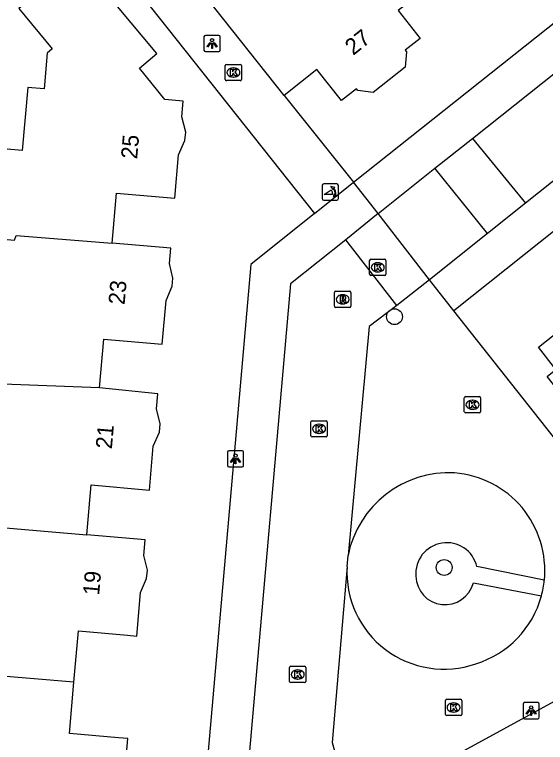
# Model space of a CAD drawing. Extents: x 159628 to 160723, y 388176 to 389416.
# Drawn here: x 160028.09 to 160060.72, y 388521.02 to 388565.76 of the extents above; entities that cross this region are included whole.
import ezdxf

# ---------------------------------------------------------------- set-up
doc = ezdxf.new("R2010")
doc.units = 0
for name, color, linetype in [('IMGEO_Boom', 7, 'Continuous'), ('IMGEO_Kolk', 7, 'Continuous'), ('IMGEO_Lichtpunt', 7, 'Continuous'), ('IMGEO_Pand', 7, 'Continuous'), ('IMGEO_Pand_nummerreeks', 7, 'Continuous'), ('IMGEO_Poller', 7, 'Continuous'), ('IMGEO_Rijbaan_lokaal_open', 7, 'Continuous'), ('IMGEO_Rioolput', 7, 'Continuous'), ('IMGEO_Voetpad_halfverhard', 7, 'Continuous'), ('IMGEO_Voetpad_open', 7, 'Continuous')]:
    doc.layers.add(name, color=color, linetype=linetype)

msp = doc.modelspace()

# ---------------------------------------------------------------- linework, layer by layer
at = {"layer": 'IMGEO_Boom'}
for centre in [(160051.439, 388547.193), (160054.494, 388531.775)]:
    msp.add_circle(centre, 0.489, dxfattribs=at)
at = {"layer": 'IMGEO_Kolk'}
for p, q in [((160041.035, 388561.774), (160041.035, 388562.626)), ((160041.11, 388562.7), (160041.962, 388562.7)), ((160041.523, 388562.48), (160041.548, 388562.48)), ((160042.036, 388562.626), (160042.036, 388561.774)), ((160041.962, 388561.7), (160041.11, 388561.7)), ((160041.546, 388561.92), (160041.521, 388561.92)), ((160049.912, 388549.798), (160049.912, 388550.65)), ((160049.987, 388550.724), (160050.839, 388550.724)), ((160050.4, 388550.504), (160050.425, 388550.504)), ((160050.913, 388550.65), (160050.913, 388549.798)), ((160050.423, 388549.944), (160050.398, 388549.944)), ((160050.839, 388549.724), (160049.987, 388549.724)), ((160055.731, 388541.354), (160055.731, 388542.206)), ((160055.806, 388542.28), (160056.658, 388542.28)), ((160056.219, 388542.06), (160056.244, 388542.06)), ((160056.732, 388542.206), (160056.732, 388541.354)), ((160056.242, 388541.5), (160056.217, 388541.5)), ((160056.658, 388541.28), (160055.806, 388541.28)), ((160046.304, 388539.874), (160046.304, 388540.726)), ((160046.379, 388540.8), (160047.231, 388540.8)), ((160046.792, 388540.58), (160046.817, 388540.58)), ((160047.305, 388540.726), (160047.305, 388539.874)), ((160047.231, 388539.8), (160046.379, 388539.8)), ((160046.815, 388540.02), (160046.79, 388540.02)), ((160044.989, 388524.776), (160044.989, 388525.628)), ((160045.064, 388525.702), (160045.916, 388525.702)), ((160045.477, 388525.482), (160045.502, 388525.482)), ((160045.99, 388525.628), (160045.99, 388524.776)), ((160045.5, 388524.922), (160045.475, 388524.922)), ((160045.916, 388524.702), (160045.064, 388524.702)), ((160054.571, 388522.747), (160054.571, 388523.599)), ((160054.646, 388523.673), (160055.498, 388523.673)), ((160055.572, 388523.599), (160055.572, 388522.747)), ((160055.059, 388523.453), (160055.084, 388523.453)), ((160055.498, 388522.673), (160054.646, 388522.673)), ((160055.082, 388522.893), (160055.057, 388522.893))]:
    msp.add_line(p, q, dxfattribs=at)
for points in [[(160041.035, 388561.774), (160041.035, 388562.626)], [(160041.11, 388562.7), (160041.962, 388562.7)], [(160042.036, 388562.626), (160042.036, 388561.774)], [(160041.356, 388562.4), (160041.479, 388562.4), (160041.479, 388562.249), (160041.609, 388562.4), (160041.773, 388562.4), (160041.627, 388562.249), (160041.78, 388562), (160041.628, 388562), (160041.543, 388562.164), (160041.479, 388562.097), (160041.479, 388562), (160041.356, 388562), (160041.356, 388562.4)], [(160041.962, 388561.7), (160041.11, 388561.7)], [(160049.912, 388549.798), (160049.912, 388550.65)], [(160049.987, 388550.724), (160050.839, 388550.724)], [(160050.233, 388550.424), (160050.356, 388550.424), (160050.356, 388550.273), (160050.486, 388550.424), (160050.65, 388550.424), (160050.504, 388550.273), (160050.657, 388550.024), (160050.505, 388550.024), (160050.42, 388550.188), (160050.356, 388550.121), (160050.356, 388550.024), (160050.233, 388550.024), (160050.233, 388550.424)], [(160050.913, 388550.65), (160050.913, 388549.798)], [(160050.839, 388549.724), (160049.987, 388549.724)], [(160055.731, 388541.354), (160055.731, 388542.206)], [(160055.806, 388542.28), (160056.658, 388542.28)], [(160056.052, 388541.98), (160056.175, 388541.98), (160056.175, 388541.829), (160056.305, 388541.98), (160056.469, 388541.98), (160056.323, 388541.829), (160056.476, 388541.58), (160056.324, 388541.58), (160056.239, 388541.744), (160056.175, 388541.677), (160056.175, 388541.58), (160056.052, 388541.58), (160056.052, 388541.98)], [(160056.732, 388542.206), (160056.732, 388541.354)], [(160056.658, 388541.28), (160055.806, 388541.28)], [(160046.304, 388539.874), (160046.304, 388540.726)], [(160046.379, 388540.8), (160047.231, 388540.8)], [(160047.305, 388540.726), (160047.305, 388539.874)], [(160046.625, 388540.5), (160046.748, 388540.5), (160046.748, 388540.349), (160046.878, 388540.5), (160047.042, 388540.5), (160046.896, 388540.349), (160047.049, 388540.1), (160046.897, 388540.1), (160046.812, 388540.264), (160046.748, 388540.197), (160046.748, 388540.1), (160046.625, 388540.1), (160046.625, 388540.5)], [(160047.231, 388539.8), (160046.379, 388539.8)], [(160044.989, 388524.776), (160044.989, 388525.628)], [(160045.064, 388525.702), (160045.916, 388525.702)], [(160045.31, 388525.402), (160045.433, 388525.402), (160045.433, 388525.251), (160045.563, 388525.402), (160045.727, 388525.402), (160045.581, 388525.251), (160045.734, 388525.002), (160045.582, 388525.002), (160045.497, 388525.166), (160045.433, 388525.099), (160045.433, 388525.002), (160045.31, 388525.002), (160045.31, 388525.402)], [(160045.99, 388525.628), (160045.99, 388524.776)], [(160045.916, 388524.702), (160045.064, 388524.702)], [(160054.571, 388522.747), (160054.571, 388523.599)], [(160054.646, 388523.673), (160055.498, 388523.673)], [(160055.572, 388523.599), (160055.572, 388522.747)], [(160054.892, 388523.373), (160055.015, 388523.373), (160055.015, 388523.222), (160055.145, 388523.373), (160055.309, 388523.373), (160055.163, 388523.222), (160055.316, 388522.973), (160055.164, 388522.973), (160055.079, 388523.137), (160055.015, 388523.07), (160055.015, 388522.973), (160054.892, 388522.973), (160054.892, 388523.373)], [(160055.498, 388522.673), (160054.646, 388522.673)]]:
    msp.add_lwpolyline(points, dxfattribs=at)
for centre, start, end in [((160041.112, 388562.624), 91.552, 178.448), ((160041.112, 388562.624), 91.552, 178.448), ((160041.96, 388562.624), 1.552, 88.448), ((160041.96, 388562.624), 1.552, 88.448), ((160041.112, 388561.776), 181.552, 268.448), ((160041.112, 388561.776), 181.552, 268.448), ((160041.96, 388561.776), 271.552, 358.448), ((160041.96, 388561.776), 271.552, 358.448), ((160049.989, 388550.648), 91.552, 178.448), ((160049.989, 388550.648), 91.552, 178.448), ((160050.837, 388550.648), 1.552, 88.448), ((160050.837, 388550.648), 1.552, 88.448), ((160049.989, 388549.8), 181.552, 268.448), ((160049.989, 388549.8), 181.552, 268.448), ((160050.837, 388549.8), 271.552, 358.448), ((160050.837, 388549.8), 271.552, 358.448), ((160055.808, 388542.204), 91.552, 178.448), ((160055.808, 388542.204), 91.552, 178.448), ((160056.656, 388542.204), 1.552, 88.448), ((160056.656, 388542.204), 1.552, 88.448), ((160055.808, 388541.356), 181.552, 268.448), ((160055.808, 388541.356), 181.552, 268.448), ((160056.656, 388541.356), 271.552, 358.448), ((160056.656, 388541.356), 271.552, 358.448), ((160046.381, 388540.724), 91.552, 178.448), ((160046.381, 388540.724), 91.552, 178.448), ((160047.229, 388540.724), 1.552, 88.448), ((160047.229, 388540.724), 1.552, 88.448), ((160046.381, 388539.876), 181.552, 268.448), ((160046.381, 388539.876), 181.552, 268.448), ((160047.229, 388539.876), 271.552, 358.448), ((160047.229, 388539.876), 271.552, 358.448), ((160045.066, 388525.626), 91.552, 178.448), ((160045.066, 388525.626), 91.552, 178.448), ((160045.914, 388525.626), 1.552, 88.448), ((160045.914, 388525.626), 1.552, 88.448), ((160045.066, 388524.778), 181.552, 268.448), ((160045.066, 388524.778), 181.552, 268.448), ((160045.914, 388524.778), 271.552, 358.448), ((160045.914, 388524.778), 271.552, 358.448), ((160054.648, 388523.597), 91.552, 178.448), ((160054.648, 388523.597), 91.552, 178.448), ((160055.496, 388523.597), 1.552, 88.448), ((160055.496, 388523.597), 1.552, 88.448), ((160054.648, 388522.749), 181.552, 268.448), ((160054.648, 388522.749), 181.552, 268.448), ((160055.496, 388522.749), 271.552, 358.448), ((160055.496, 388522.749), 271.552, 358.448)]:
    msp.add_arc(centre, 0.0765, start, end, dxfattribs=at)
for centre, major_axis, ratio, start_param, end_param in [((160041.522, 388562.2), (-0.387, 0.002), 0.722429, 4.712389, 7.853982), ((160041.547, 388562.2), (-0.39, 0.002), 0.717154, 1.570796, 4.712389), ((160050.399, 388550.224), (-0.387, 0.002), 0.722429, 4.712389, 7.853982), ((160050.424, 388550.224), (-0.39, 0.002), 0.717154, 1.570796, 4.712389), ((160056.218, 388541.78), (-0.387, 0.002), 0.722429, 4.712389, 7.853982), ((160056.243, 388541.78), (-0.39, 0.002), 0.717154, 1.570796, 4.712389), ((160046.791, 388540.3), (-0.387, 0.002), 0.722429, 4.712389, 7.853982), ((160046.816, 388540.3), (-0.39, 0.002), 0.717154, 1.570796, 4.712389), ((160045.476, 388525.202), (-0.387, 0.002), 0.722429, 4.712389, 7.853982), ((160045.501, 388525.202), (-0.39, 0.002), 0.717154, 1.570796, 4.712389), ((160055.058, 388523.173), (-0.387, 0.002), 0.722429, 4.712389, 7.853982), ((160055.083, 388523.173), (-0.39, 0.002), 0.717154, 1.570796, 4.712389)]:
    msp.add_ellipse(centre, major_axis=major_axis, ratio=ratio, start_param=start_param, end_param=end_param, dxfattribs=at)
at = {"layer": 'IMGEO_Lichtpunt'}
for p, q in [((160039.73, 388564.39), (160039.73, 388563.583)), ((160039.73, 388564.39), (160039.73, 388563.583)), ((160040.632, 388564.485), (160039.824, 388564.485)), ((160040.632, 388564.485), (160039.824, 388564.485)), ((160040.726, 388563.583), (160040.726, 388564.39)), ((160040.726, 388563.583), (160040.726, 388564.39)), ((160039.824, 388563.489), (160040.632, 388563.489)), ((160039.824, 388563.489), (160040.632, 388563.489)), ((160041.17, 388538.86), (160041.17, 388538.053)), ((160041.17, 388538.86), (160041.17, 388538.053)), ((160042.072, 388538.955), (160041.264, 388538.955)), ((160042.072, 388538.955), (160041.264, 388538.955)), ((160042.166, 388538.053), (160042.166, 388538.86)), ((160042.166, 388538.053), (160042.166, 388538.86)), ((160041.264, 388537.959), (160042.072, 388537.959)), ((160041.264, 388537.959), (160042.072, 388537.959)), ((160059.341, 388523.378), (160059.341, 388522.571)), ((160059.341, 388523.378), (160059.341, 388522.571)), ((160060.243, 388523.473), (160059.435, 388523.473)), ((160060.243, 388523.473), (160059.435, 388523.473)), ((160060.337, 388522.571), (160060.337, 388523.378)), ((160060.337, 388522.571), (160060.337, 388523.378)), ((160059.435, 388522.477), (160060.243, 388522.477)), ((160059.435, 388522.477), (160060.243, 388522.477))]:
    msp.add_line(p, q, dxfattribs=at)
for points in [[(160040.104, 388564.054), (160040.143, 388564.026), (160039.955, 388563.764), (160039.917, 388563.791), (160040.104, 388564.054)], [(160040.206, 388564.006), (160040.253, 388564.006), (160040.253, 388563.684), (160040.206, 388563.684), (160040.206, 388564.006)], [(160040.316, 388564.026), (160040.354, 388564.053), (160040.541, 388563.791), (160040.502, 388563.763), (160040.316, 388564.026)], [(160041.544, 388538.524), (160041.583, 388538.496), (160041.395, 388538.234), (160041.357, 388538.261), (160041.544, 388538.524)], [(160041.646, 388538.476), (160041.693, 388538.476), (160041.693, 388538.154), (160041.646, 388538.154), (160041.646, 388538.476)], [(160041.756, 388538.496), (160041.794, 388538.523), (160041.981, 388538.261), (160041.942, 388538.233), (160041.756, 388538.496)], [(160059.715, 388523.042), (160059.754, 388523.014), (160059.566, 388522.752), (160059.528, 388522.779), (160059.715, 388523.042)], [(160059.817, 388522.994), (160059.864, 388522.994), (160059.864, 388522.672), (160059.817, 388522.672), (160059.817, 388522.994)], [(160059.927, 388523.014), (160059.965, 388523.041), (160060.152, 388522.779), (160060.113, 388522.751), (160059.927, 388523.014)]]:
    msp.add_lwpolyline(points, dxfattribs=at)
for centre in [(160040.229, 388564.188), (160041.669, 388538.658), (160059.84, 388523.176)]:
    msp.add_circle(centre, 0.0994, dxfattribs=at)
for centre, start, end in [((160039.824, 388564.39), 90, 180), ((160039.824, 388564.39), 90, 180), ((160040.632, 388564.39), 0, 90), ((160040.632, 388564.39), 0, 90), ((160039.824, 388563.583), 180, 270), ((160039.824, 388563.583), 180, 270), ((160040.632, 388563.583), 270, 0), ((160040.632, 388563.583), 270, 360), ((160041.264, 388538.86), 90, 180), ((160041.264, 388538.86), 90, 180), ((160042.072, 388538.86), 0, 90), ((160042.072, 388538.86), 0, 90), ((160041.264, 388538.053), 180, 270), ((160041.264, 388538.053), 180, 270), ((160042.072, 388538.053), 270, 0), ((160042.072, 388538.053), 270, 360), ((160059.435, 388523.378), 90, 180), ((160059.435, 388523.378), 90, 180), ((160060.243, 388523.378), 0, 90), ((160060.243, 388523.378), 0, 90), ((160059.435, 388522.571), 180, 270), ((160059.435, 388522.571), 180, 270), ((160060.243, 388522.571), 270, 0), ((160060.243, 388522.571), 270, 360)]:
    msp.add_arc(centre, 0.0946, start, end, dxfattribs=at)
at = {"layer": 'IMGEO_Pand'}
for points in [[(160034.086, 388551.708), (160034.354, 388554.784), (160037.94, 388554.471), (160038.171, 388557.131), (160038.561, 388558.032), (160038.604, 388558.53), (160038.376, 388559.484), (160038.46, 388560.448), (160037.324, 388560.547), (160035.77, 388562.476), (160036.828, 388563.366), (160031.991, 388569.166), (160028.349, 388566.128), (160030.408, 388563.647), (160030.093, 388563.385), (160029.897, 388561.194), (160028.896, 388561.281), (160028.559, 388557.414), (160026.466, 388557.595), (160026.033, 388552.614), (160025.986, 388552.075), (160028.078, 388551.893)], [(160054.823, 388568.499), (160051.661, 388566.005), (160053.013, 388564.293), (160052.104, 388563.574), (160052.185, 388563.473), (160052.09, 388562.53), (160050.13, 388560.979), (160049.19, 388561.103), (160049.109, 388561.204), (160048.183, 388560.471), (160046.67, 388562.385), (160044.656, 388560.791)], [(160044.656, 388560.791), (160039.84, 388566.876)], [(160063.86, 388540.799), (160063.507, 388541.245), (160062.958, 388540.81), (160060.817, 388543.515), (160061.365, 388543.949), (160060.285, 388545.313), (160064.622, 388548.745), (160062.73, 388551.137), (160061.52, 388552.667)], [(160028.078, 388551.893), (160028.18, 388552.188), (160034.086, 388551.708)], [(160033.313, 388542.829), (160033.573, 388545.818), (160037.159, 388545.505), (160037.402, 388548.192), (160037.78, 388549.066), (160037.823, 388549.564), (160037.609, 388550.46), (160037.695, 388551.414), (160034.086, 388551.708)], [(160033.313, 388542.829), (160025.206, 388543.13)], [(160032.525, 388533.786), (160032.792, 388536.852), (160036.378, 388536.539), (160036.613, 388539.228), (160036.99, 388540.1), (160037.033, 388540.598), (160036.812, 388541.521), (160036.894, 388542.455), (160033.313, 388542.829)], [(160026.524, 388533.946), (160026.568, 388534.289), (160032.525, 388533.786)], [(160031.736, 388524.73), (160032.01, 388527.876), (160035.03, 388527.612), (160035.596, 388527.563), (160035.829, 388530.233), (160036.206, 388531.104), (160036.249, 388531.602), (160036.029, 388532.522), (160036.112, 388533.483), (160032.525, 388533.786)], [(160023.661, 388525.398), (160023.197, 388520.059), (160025.29, 388519.877), (160024.963, 388516.122), (160034.527, 388515.289), (160034.616, 388516.302), (160034.993, 388517.173), (160035.036, 388517.671), (160034.815, 388518.594), (160035.048, 388521.267), (160034.481, 388521.316), (160031.462, 388521.58), (160031.736, 388524.73)], [(160031.736, 388524.73), (160023.661, 388525.398)]]:
    msp.add_lwpolyline(points, dxfattribs=at)
at = {"layer": 'IMGEO_Poller'}
for p, q in [((160047.896, 388555.349), (160047.088, 388555.349)), ((160047.896, 388555.349), (160047.088, 388555.349)), ((160046.994, 388555.254), (160046.994, 388554.447)), ((160046.994, 388555.254), (160046.994, 388554.447)), ((160047.99, 388554.447), (160047.99, 388555.254)), ((160047.99, 388554.447), (160047.99, 388555.254)), ((160047.088, 388554.352), (160047.896, 388554.352)), ((160047.088, 388554.352), (160047.896, 388554.352))]:
    msp.add_line(p, q, dxfattribs=at)
for points in [[(160047.629, 388554.705), (160047.116, 388554.705), (160047.546, 388554.98)], [(160047.673, 388555.078), (160047.661, 388555.005), (160047.536, 388555.21)], [(160047.536, 388555.21), (160047.767, 388555.144), (160047.696, 388555.112)], [(160047.689, 388554.533), (160047.755, 388554.764), (160047.785, 388554.696)], [(160047.821, 388554.669), (160047.893, 388554.658), (160047.689, 388554.533)]]:
    msp.add_lwpolyline(points, dxfattribs=at)
for centre, radius, start, end in [((160047.088, 388555.254), 0.0946, 90, 180), ((160047.088, 388555.254), 0.0946, 90, 180), ((160047.896, 388555.254), 0.0946, 0, 90), ((160047.896, 388555.254), 0.0946, 0, 90), ((160047.301, 388554.755), 0.332, 351.3247, 42.4854), ((160047.315, 388554.765), 0.476, 351.7527, 41.1691), ((160047.315, 388554.765), 0.516, 349.3569, 42.2912), ((160047.088, 388554.447), 0.0946, 180, 270), ((160047.088, 388554.447), 0.0946, 180, 270), ((160047.896, 388554.447), 0.0946, 270, 0), ((160047.896, 388554.447), 0.0946, 270, 0)]:
    msp.add_arc(centre, radius, start, end, dxfattribs=at)
at = {"layer": 'IMGEO_Rijbaan_lokaal_open'}
for points in [[(160056.239, 388558.155), (160092.364, 388586.916), (160100.44, 388593.31)], [(160103.624, 388589.256), (160098.963, 388585.587), (160059.496, 388554.167)], [(160053.924, 388556.312), (160056.239, 388558.155)], [(160056.239, 388558.155), (160059.496, 388554.167)], [(160050.426, 388553.527), (160053.924, 388556.312)], [(160057.149, 388552.298), (160053.924, 388556.312)], [(160059.496, 388554.167), (160057.149, 388552.298)], [(160050.426, 388553.527), (160048.443, 388551.926)], [(160053.589, 388549.464), (160050.426, 388553.527)], [(160057.149, 388552.298), (160053.589, 388549.464)], [(160048.443, 388551.926), (160045.044, 388549.209), (160042.532, 388520.479), (160043.615, 388516.712)], [(160051.58, 388547.883), (160048.443, 388551.926)], [(160053.589, 388549.464), (160051.58, 388547.883)], [(160051.58, 388547.883), (160049.877, 388546.582), (160048.583, 388532.514)], [(160048.523, 388531.842), (160048.583, 388532.514)], [(160048.523, 388531.842), (160047.599, 388521.019), (160048.11, 388519.2)]]:
    msp.add_lwpolyline(points, dxfattribs=at)
at = {"layer": 'IMGEO_Rioolput'}
for p, q in [((160047.753, 388547.834), (160047.753, 388548.686)), ((160047.828, 388548.76), (160048.68, 388548.76)), ((160048.754, 388548.686), (160048.754, 388547.834)), ((160048.241, 388548.54), (160048.266, 388548.54)), ((160048.68, 388547.76), (160047.828, 388547.76)), ((160048.264, 388547.98), (160048.239, 388547.98))]:
    msp.add_line(p, q, dxfattribs=at)
for points in [[(160047.753, 388547.834), (160047.753, 388548.686)], [(160047.828, 388548.76), (160048.68, 388548.76)], [(160048.754, 388548.686), (160048.754, 388547.834)], [(160048.342, 388548.458), (160048.09, 388548.46), (160048.09, 388548.06)], [(160048.09, 388548.06), (160048.214, 388548.06), (160048.214, 388548.222), (160048.225, 388548.222)], [(160048.268, 388548.379), (160048.214, 388548.379), (160048.214, 388548.298)], [(160048.214, 388548.298), (160048.266, 388548.298)], [(160048.272, 388548.193), (160048.343, 388548.06), (160048.483, 388548.06), (160048.418, 388548.186)], [(160048.68, 388547.76), (160047.828, 388547.76)]]:
    msp.add_lwpolyline(points, dxfattribs=at)
for centre, radius, start, end in [((160047.83, 388548.684), 0.0765, 91.552, 178.448), ((160047.83, 388548.684), 0.0765, 91.552, 178.448), ((160048.678, 388548.684), 0.0765, 1.552, 88.448), ((160048.678, 388548.684), 0.0765, 1.552, 88.448), ((160048.224, 388548.169), 0.0533, 26.0293, 88.6989), ((160048.25, 388548.487), 0.19, 274.7715, 282.9687), ((160048.274, 388548.283), 0.0964, 77.0061, 93.1865), ((160048.288, 388548.34), 0.0378, 276.6634, 79.6772), ((160048.341, 388548.348), 0.109, 350.3612, 89.416), ((160048.339, 388548.348), 0.112, 277.5842, 350.9817), ((160048.323, 388548.133), 0.108, 29.5134, 73.7905), ((160047.83, 388547.836), 0.0765, 181.552, 268.448), ((160047.83, 388547.836), 0.0765, 181.552, 268.448), ((160048.678, 388547.836), 0.0765, 271.552, 358.448), ((160048.678, 388547.836), 0.0765, 271.552, 358.448)]:
    msp.add_arc(centre, radius, start, end, dxfattribs=at)
for centre, major_axis, ratio, start_param, end_param in [((160048.24, 388548.26), (-0.387, 0.002), 0.722429, 4.712389, 7.853982), ((160048.265, 388548.26), (-0.39, 0.002), 0.717154, 1.570796, 4.712389)]:
    msp.add_ellipse(centre, major_axis=major_axis, ratio=ratio, start_param=start_param, end_param=end_param, dxfattribs=at)
at = {"layer": 'IMGEO_Voetpad_halfverhard'}
for points in [[(160060.648, 388531.003), (160056.503, 388531.833)], [(160056.285, 388530.833), (160060.47, 388530.031)]]:
    msp.add_lwpolyline(points, dxfattribs=at)
for centre, radius, start, end in [((160054.649, 388531.392), 1.906, 13.3658, 184.741), ((160054.547, 388531.29), 1.798, 181.7659, 345.2585)]:
    msp.add_arc(centre, radius, start, end, dxfattribs=at)
at = {"layer": 'IMGEO_Voetpad_open'}
for points in [[(160048.914, 388555.466), (160093.106, 388590.577), (160107.647, 388602.096), (160111.88, 388605.45), (160116.132, 388608.831)], [(160010.998, 388598.278), (160046.524, 388553.531)], [(160044.656, 388560.791), (160048.914, 388555.466)], [(160046.524, 388553.531), (160048.914, 388555.466)], [(160050.426, 388553.527), (160048.914, 388555.466)], [(160046.524, 388553.531), (160042.618, 388550.4), (160039.957, 388520.258), (160041.197, 388515.977)], [(160061.52, 388552.667), (160055.092, 388547.547)], [(160055.092, 388547.547), (160053.589, 388549.464)], [(160068.183, 388531), (160055.092, 388547.547)], [(160051.036, 388517.975), (160068.858, 388527.703)]]:
    msp.add_lwpolyline(points, dxfattribs=at)
for centre, radius, start, end in [((160054.778, 388531.279), 6.316, 86.7841, 168.7293), ((160054.676, 388531.601), 6.002, 354.2778, 85.6425), ((160054.483, 388531.498), 5.97, 176.6989, 289.1873), ((160054.733, 388531.584), 5.943, 344.8537, 354.3914), ((160054.675, 388531.596), 6.003, 287.1531, 344.888)]:
    msp.add_arc(centre, radius, start, end, dxfattribs=at)

# ---------------------------------------------------------------- texts
at = {"layer": 'IMGEO_Pand_nummerreeks'}
for s, rotation, p in [('27', 38.3555, (160048.898, 388563.218)), ('25', 85.0269, (160035.618, 388556.854)), ('23', 84.8149, (160034.846, 388547.897)), ('21', 85.0155, (160034.066, 388539.035)), ('19', 85.0155, (160033.282, 388530.037))]:
    msp.add_text(s, height=1, rotation=rotation, dxfattribs=at).set_placement(p)

doc.saveas('drawing.dxf')
